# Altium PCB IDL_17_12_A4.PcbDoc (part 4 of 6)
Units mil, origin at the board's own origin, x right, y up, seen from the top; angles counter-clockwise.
Board outline 3172.06 x 10350 mil, 6 copper layers (Top Signal, Mid Signal, 3.3 Volt, GND, 5 Volt, Bot Signal), stack 122.8 mil thick; 332 components, 120 nets, 1937 pads, 197 vias.
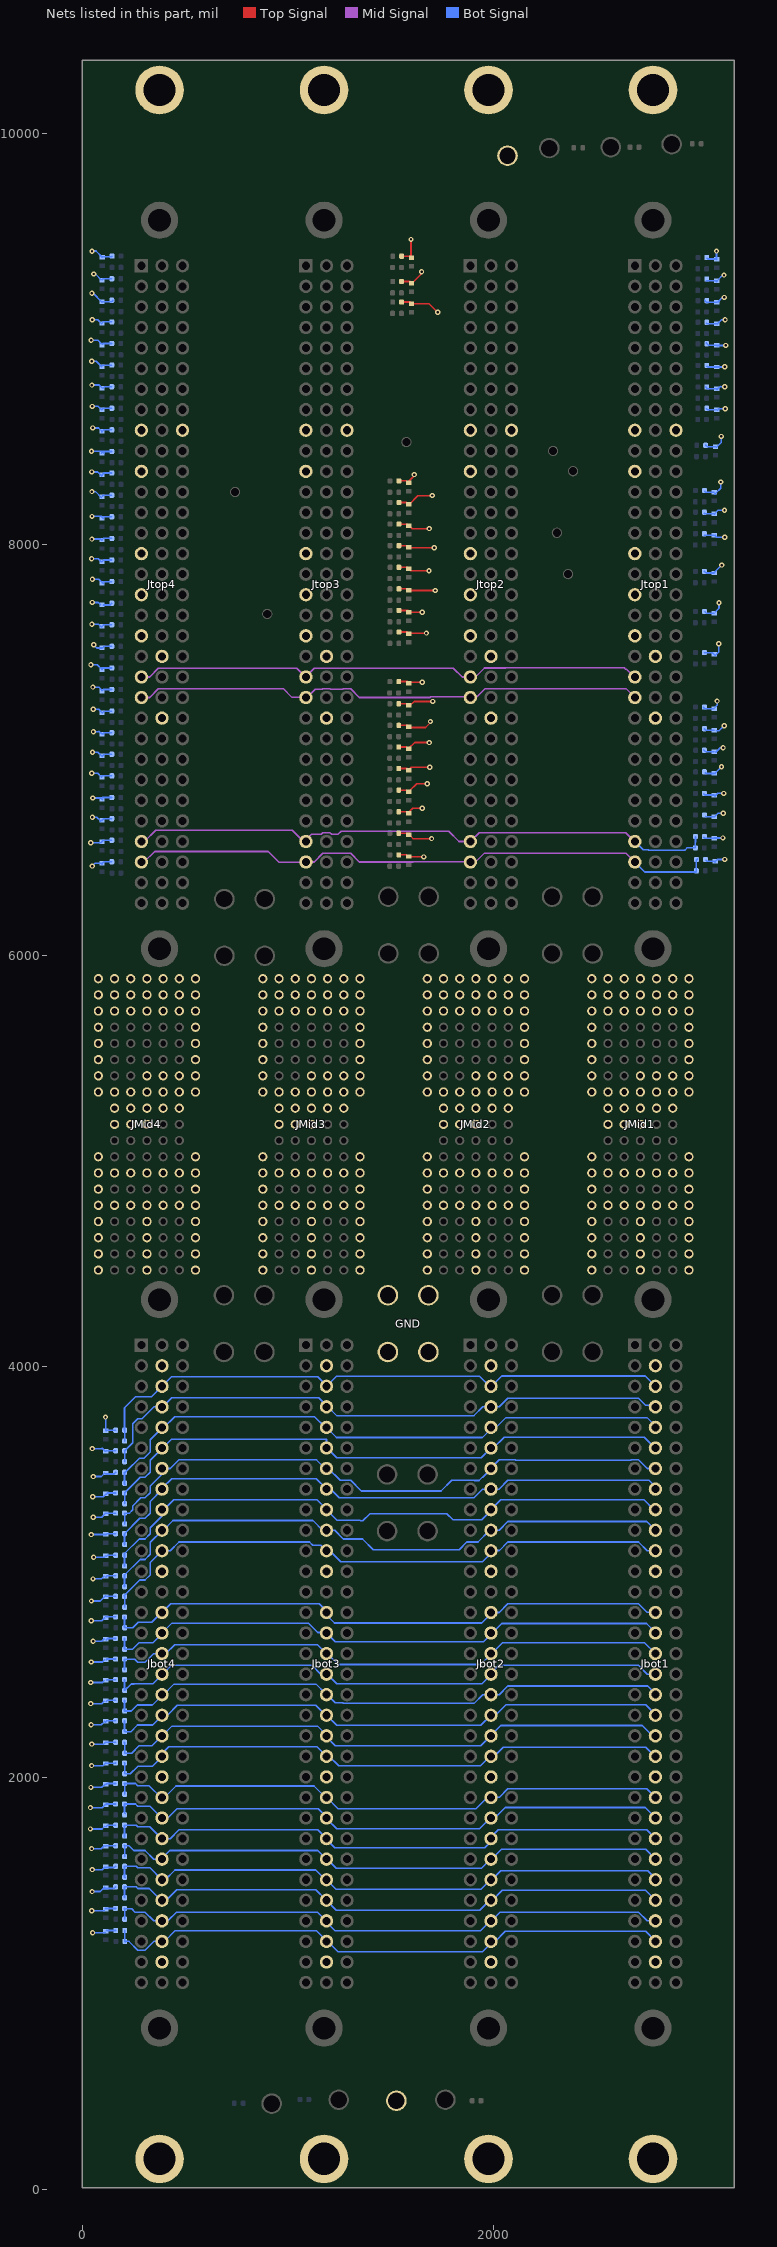
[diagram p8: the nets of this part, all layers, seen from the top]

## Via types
v1: diameter 25.59, hole 12, Top Signal to Bot Signal, 197 vias

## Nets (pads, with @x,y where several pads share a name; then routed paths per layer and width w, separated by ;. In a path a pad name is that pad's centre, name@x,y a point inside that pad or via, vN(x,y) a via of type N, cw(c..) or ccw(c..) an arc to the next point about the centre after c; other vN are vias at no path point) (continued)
GND: CR_IDL_17_12_TerA1.1 CR_IDL_17_12_TerA2.1 CR_IDL_17_12_TerA3.1 CR_IDL_17_12_TerA4.1 CR_IDL_17_12_TerA5.1 CR_IDL_17_12_TerA6.1 CR_IDL_17_12_TerA7.1 CR_IDL_17_12_TerA8.1 CR_IDL_17_12_TerA9.1 CR_IDL_17_12_TerA10.1 CR_IDL_17_12_TerA11.1 CR_IDL_17_12_TerA12.1 CR_IDL_17_12_TerA13.1 CR_IDL_17_12_TerA14.1 CR_IDL_17_12_TerA15.1 CR_IDL_17_12_TerA16.1 CR_IDL_17_12_TerA17.1 CR_IDL_17_12_TerA18.1 CR_IDL_17_12_TerA19.1 CR_IDL_17_12_TerA20.1 CR_IDL_17_12_TerA21.1 CR_IDL_17_12_TerA22.1 CR_IDL_17_12_TerA23.1 CR_IDL_17_12_TerA24.1 CR_IDL_17_12_TerA25.1 CR_IDL_17_12_TerA26.1 CR_IDL_17_12_TerA27.1 CR_IDL_17_12_TerA28.1 CR_IDL_17_12_TerA29.1 CR_IDL_17_12_TerA30.1 CR_IDL_17_12_TerA31.1 CR_IDL_17_12_TerA32.1 CR_IDL_17_12_TerA33.1 CR_IDL_17_12_TerA34.1 CR_IDL_17_12_TerA35.1 CR_IDL_17_12_TerA36.1 CR_IDL_17_12_TerA37.1 CR_IDL_17_12_TerA38.1 CR_IDL_17_12_TerA39.1 CR_IDL_17_12_TerA40.1 CR_IDL_17_12_TerA41.1 CR_IDL_17_12_TerA42.1 CR_IDL_17_12_TerA43.1 CR_IDL_17_12_TerA44.1 CR_IDL_17_12_TerA45.1 CR_IDL_17_12_TerA46.1 CR_IDL_17_12_TerA47.1 CR_IDL_17_12_TerA48.1 CR_IDL_17_12_TerA49.1 CR_IDL_17_12_TerA50.1 CR_IDL_17_12_TerA51.1 CR_IDL_17_12_TerA52.1 CR_IDL_17_12_TerA53.1 CR_IDL_17_12_TerA54.1 CR_IDL_17_12_TerA55.1 CR_IDL_17_12_TerA56.1 CR_IDL_17_12_TerA57.1 CR_IDL_17_12_TerA58.1 CR_IDL_17_12_TerA59.1 CR_IDL_17_12_TerA60.1 CR_IDL_17_12_TerA61.1 CR_IDL_17_12_TerA62.1 CR_IDL_17_12_TerA63.1 CR_IDL_17_12_TerA64.1 CR_IDL_17_12_TerA65.1 CR_IDL_17_12_TerA66.1 CR_IDL_17_12_TerA67.1 CR_IDL_17_12_TerA68.1 CR_IDL_17_12_TerA69.1 CR_IDL_17_12_TerA70.1 CR_IDL_17_12_TerA71.1 CR_IDL_17_12_TerA72.1 CRB_IDL_17_12_TerB1.1 CRB_IDL_17_12_TerB2.1 CRB_IDL_17_12_TerB3.1 CRB_IDL_17_12_TerB4.1 CRB_IDL_17_12_TerB5.1 CRB_IDL_17_12_TerB6.1 CRB_IDL_17_12_TerB7.1 CRB_IDL_17_12_TerB8.1 CRB_IDL_17_12_TerB9.1 CRB_IDL_17_12_TerB10.1 CRB_IDL_17_12_TerB11.1 CRB_IDL_17_12_TerB12.1 CRB_IDL_17_12_TerB13.1 CRB_IDL_17_12_TerB14.1 CRB_IDL_17_12_TerB15.1 CRB_IDL_17_12_TerB16.1 CRB_IDL_17_12_TerB17.1 CRB_IDL_17_12_TerB18.1 CRB_IDL_17_12_TerB19.1 CRB_IDL_17_12_TerB20.1 CRB_IDL_17_12_TerB21.1 CRB_IDL_17_12_TerB22.1 CRB_IDL_17_12_TerB23.1 CRB_IDL_17_12_TerB24.1 CRB_IDL_17_12_TerB25.1 GND.1 GND.2 GND.3 GND.4 Jbot1.B2 Jbot1.B12 Jbot1.B22 Jbot1.B31 Jbot2.B2 Jbot2.B12 Jbot2.B22 Jbot2.B31 Jbot3.B2 Jbot3.B12 Jbot3.B22 Jbot3.B31 Jbot4.B2 Jbot4.B12 Jbot4.B22 Jbot4.B31 JMid1.1 JMid1.2 JMid1.3 JMid1.4 JMid1.5 JMid1.6 JMid1.7 JMid1.8 JMid1.9 JMid1.10 JMid1.11 JMid1.12 JMid1.13 JMid1.14 JMid1.15 JMid1.16 JMid1.17 JMid1.18 JMid1.19 JMid1.24 JMid1.25 JMid1.26 JMid1.29 JMid1.31 JMid1.36 JMid1.37 JMid1.38 JMid1.43 JMid1.44 JMid1.45 JMid1.48 JMid1.50 JMid1.55 JMid1.56 JMid1.57 JMid1.61 JMid1.62 JMid1.63 JMid1.64 JMid1.67 JMid1.69 JMid1.70 JMid1.71 JMid1.72 JMid1.73 JMid1.74 JMid1.75 JMid1.76 JMid1.80 JMid1.81 JMid1.82 JMid1.86 JMid1.88 JMid1.93 JMid1.94 JMid1.95 JMid1.99 JMid1.100 JMid1.101 JMid1.105 JMid1.107 JMid1.112 JMid1.113 JMid1.114 JMid1.115 JMid1.116 JMid1.117 JMid1.118 JMid1.119 JMid1.120 JMid1.121 JMid1.122 JMid1.123 JMid1.124 JMid1.125 JMid1.126 JMid1.127 JMid2.1 JMid2.2 JMid2.3 JMid2.4 JMid2.5 JMid2.6 JMid2.7 JMid2.8 JMid2.9 JMid2.10 JMid2.11 JMid2.12 JMid2.13 JMid2.14 JMid2.15 JMid2.16 JMid2.17 JMid2.18 JMid2.19 JMid2.24 JMid2.25 JMid2.26 JMid2.29 JMid2.31 JMid2.36 JMid2.37 JMid2.38 JMid2.43 JMid2.44 JMid2.45 JMid2.48 JMid2.50 JMid2.55 JMid2.56 JMid2.57 JMid2.61 JMid2.62 JMid2.63 JMid2.64 JMid2.67 JMid2.69 JMid2.70 JMid2.71 JMid2.72 JMid2.73 JMid2.74 JMid2.75 JMid2.76 JMid2.80 JMid2.81 JMid2.82 JMid2.86 JMid2.88 JMid2.93 JMid2.94 JMid2.95 JMid2.99 JMid2.100 JMid2.101 JMid2.105 JMid2.107 JMid2.112 JMid2.113 JMid2.114 JMid2.115 JMid2.116 JMid2.117 JMid2.118 JMid2.119 JMid2.120 JMid2.121 JMid2.122 JMid2.123 JMid2.124 JMid2.125 JMid2.126 JMid2.127 JMid3.1 JMid3.2 JMid3.3 JMid3.4 JMid3.5 JMid3.6 JMid3.7 JMid3.8 JMid3.9 JMid3.10 JMid3.11 JMid3.12 JMid3.13 JMid3.14 JMid3.15 JMid3.16 JMid3.17 JMid3.18 JMid3.19 JMid3.24 JMid3.25 JMid3.26 JMid3.29 JMid3.31 JMid3.36 JMid3.37 JMid3.38 JMid3.43 JMid3.44 JMid3.45 JMid3.48 JMid3.50 JMid3.55 JMid3.56 JMid3.57 JMid3.61 JMid3.62 JMid3.63 JMid3.64 JMid3.67 JMid3.69 JMid3.70 JMid3.71 JMid3.72 JMid3.73 JMid3.74 JMid3.75 JMid3.76 JMid3.80 JMid3.81 JMid3.82 JMid3.86 JMid3.88 JMid3.93 JMid3.94 JMid3.95 JMid3.99 JMid3.100 JMid3.101 JMid3.105 JMid3.107 JMid3.112 JMid3.113 JMid3.114 JMid3.115 JMid3.116 JMid3.117 JMid3.118 JMid3.119 JMid3.120 JMid3.121 JMid3.122 JMid3.123 JMid3.124 JMid3.125 JMid3.126 JMid3.127 JMid4.1 JMid4.2 JMid4.3 JMid4.4 JMid4.5 JMid4.6 JMid4.7 JMid4.8 JMid4.9 JMid4.10 JMid4.11 JMid4.12 JMid4.13 JMid4.14 JMid4.15 JMid4.16 JMid4.17 JMid4.18 JMid4.19 JMid4.24 JMid4.25 JMid4.26 JMid4.29 JMid4.31 JMid4.36 JMid4.37 JMid4.38 JMid4.43 JMid4.44 JMid4.45 JMid4.48 JMid4.50 JMid4.55 JMid4.56 JMid4.57 JMid4.61 JMid4.62 JMid4.63 JMid4.64 JMid4.67 JMid4.69 JMid4.70 JMid4.71 JMid4.72 JMid4.73 JMid4.74 JMid4.75 JMid4.76 JMid4.80 JMid4.81 JMid4.82 JMid4.86 JMid4.88 JMid4.93 JMid4.94 JMid4.95 JMid4.99 JMid4.100 JMid4.101 JMid4.105 JMid4.107 JMid4.112 JMid4.113 JMid4.114 JMid4.115 JMid4.116 JMid4.117 JMid4.118 JMid4.119 JMid4.120 JMid4.121 JMid4.122 JMid4.123 JMid4.124 JMid4.125 JMid4.126 JMid4.127 Jtop1.A9 Jtop1.A11 Jtop1.A15 Jtop1.A17 Jtop1.A19 Jtop1.B20 Jtop1.B23 Jtop1.C9 Jtop2.A9 Jtop2.A11 Jtop2.A15 Jtop2.A17 Jtop2.A19 Jtop2.B20 Jtop2.B23 Jtop2.C9 Jtop3.A9 Jtop3.A11 Jtop3.A15 Jtop3.A17 Jtop3.A19 Jtop3.B20 Jtop3.B23 Jtop3.C9 Jtop4.A9 Jtop4.A11 Jtop4.A15 Jtop4.A17 Jtop4.A19 Jtop4.B20 Jtop4.B23 Jtop4.C9 pad.M3 R2R_IDL_17_12_TerA1.1 R2R_IDL_17_12_TerA2.1 R2R_IDL_17_12_TerA3.1 R2R_IDL_17_12_TerA4.1 R2R_IDL_17_12_TerA5.1 R2R_IDL_17_12_TerA6.1 R2R_IDL_17_12_TerA7.1 R2R_IDL_17_12_TerA8.1 R2R_IDL_17_12_TerA9.1 R2R_IDL_17_12_TerA10.1 R2R_IDL_17_12_TerA11.1 R2R_IDL_17_12_TerA12.1 R2R_IDL_17_12_TerA13.1 R2R_IDL_17_12_TerA14.1 R2R_IDL_17_12_TerA15.1 R2R_IDL_17_12_TerA16.1 R2R_IDL_17_12_TerA17.1 R2R_IDL_17_12_TerA18.1 R2R_IDL_17_12_TerA19.1 R2R_IDL_17_12_TerA20.1 R2R_IDL_17_12_TerA21.1 R2R_IDL_17_12_TerA22.1 R2R_IDL_17_12_TerA23.1 R2R_IDL_17_12_TerA24.1 R2R_IDL_17_12_TerA25.1 R2R_IDL_17_12_TerA26.1 R2R_IDL_17_12_TerA27.1 R2R_IDL_17_12_TerA28.1 R2R_IDL_17_12_TerA29.1 R2R_IDL_17_12_TerA30.1 R2R_IDL_17_12_TerA31.1 R2R_IDL_17_12_TerA32.1 R2R_IDL_17_12_TerA33.1 R2R_IDL_17_12_TerA34.1 R2R_IDL_17_12_TerA35.1 R2R_IDL_17_12_TerA36.1 R2R_IDL_17_12_TerA37.1 R2R_IDL_17_12_TerA38.1 R2R_IDL_17_12_TerA39.1 R2R_IDL_17_12_TerA40.1 R2R_IDL_17_12_TerA41.1 R2R_IDL_17_12_TerA42.1 R2R_IDL_17_12_TerA43.1 R2R_IDL_17_12_TerA44.1 R2R_IDL_17_12_TerA45.1 R2R_IDL_17_12_TerA46.1 R2R_IDL_17_12_TerA47.1 R2R_IDL_17_12_TerA48.1 R2R_IDL_17_12_TerA49.1 R2R_IDL_17_12_TerA50.1 R2R_IDL_17_12_TerA51.1 R2R_IDL_17_12_TerA52.1 R2R_IDL_17_12_TerA53.1 R2R_IDL_17_12_TerA54.1 R2R_IDL_17_12_TerA55.1 R2R_IDL_17_12_TerA56.1 R2R_IDL_17_12_TerA57.1 R2R_IDL_17_12_TerA58.1 R2R_IDL_17_12_TerA59.1 R2R_IDL_17_12_TerA60.1 R2R_IDL_17_12_TerA61.1 R2R_IDL_17_12_TerA62.1 R2R_IDL_17_12_TerA63.1 R2R_IDL_17_12_TerA64.1 R2R_IDL_17_12_TerA65.1 R2R_IDL_17_12_TerA66.1 R2R_IDL_17_12_TerA67.1 R2R_IDL_17_12_TerA68.1 R2R_IDL_17_12_TerA69.1 R2R_IDL_17_12_TerA70.1 R2R_IDL_17_12_TerA71.1 R2R_IDL_17_12_TerA72.1 R2RB_IDL_17_12_TerB1.1 R2RB_IDL_17_12_TerB2.1 R2RB_IDL_17_12_TerB3.1 R2RB_IDL_17_12_TerB4.1 R2RB_IDL_17_12_TerB5.1 R2RB_IDL_17_12_TerB6.1 R2RB_IDL_17_12_TerB7.1 R2RB_IDL_17_12_TerB8.1 R2RB_IDL_17_12_TerB9.1 R2RB_IDL_17_12_TerB10.1 R2RB_IDL_17_12_TerB11.1 R2RB_IDL_17_12_TerB12.1 R2RB_IDL_17_12_TerB13.1 R2RB_IDL_17_12_TerB14.1 R2RB_IDL_17_12_TerB15.1 R2RB_IDL_17_12_TerB16.1 R2RB_IDL_17_12_TerB17.1 R2RB_IDL_17_12_TerB18.1 R2RB_IDL_17_12_TerB19.1 R2RB_IDL_17_12_TerB20.1 R2RB_IDL_17_12_TerB21.1 R2RB_IDL_17_12_TerB22.1 R2RB_IDL_17_12_TerB23.1 R2RB_IDL_17_12_TerB24.1 R2RB_IDL_17_12_TerB25.1 | length 11341.6
  Top Signal w8: R2R_IDL_17_12_TerA24.1@1539.78,6489.66 1577.33,6489.66 CR_IDL_17_12_TerA24.1@1586.48,6480.51 ; R2R_IDL_17_12_TerA25.1@1539.78,6594.66 1587.86,6594.66 CR_IDL_17_12_TerA25.1@1593.87,6594.66 ; R2R_IDL_17_12_TerA26.1@1539.78,6699.66 1581.86,6699.66 1588.74,6692.77 CR_IDL_17_12_TerA26.1@1589.45,6692.07 ; R2R_IDL_17_12_TerA27.1@1539.78,6804.66 1577.23,6804.66 1586.43,6795.46 CR_IDL_17_12_TerA27.1@1586.49,6795.4 ; R2R_IDL_17_12_TerA28.1@1539.78,6909.66 1579.99,6909.66 CR_IDL_17_12_TerA28.1@1584.99,6904.66 ; R2R_IDL_17_12_TerA29.1@1539.78,7014.66 1576.84,7014.66 CR_IDL_17_12_TerA29.1@1586,7005.49 ; R2R_IDL_17_12_TerA30.1@1539.78,7119.66 1584.02,7119.66 1589.83,7113.85 CR_IDL_17_12_TerA30.1@1591.41,7112.27 ; R2R_IDL_17_12_TerA31.1@1539.78,7224.66 1582.35,7224.66 CR_IDL_17_12_TerA31.1@1587.97,7219.04 ; R2R_IDL_17_12_TerA32.1@1539.78,7332.66 1582.31,7332.66 CR_IDL_17_12_TerA32.1@1588.43,7326.54 ; R2R_IDL_17_12_TerA33.1@1540.73,7573.55 1581.12,7573.55 CR_IDL_17_12_TerA33.1@1586.05,7568.62 ; R2R_IDL_17_12_TerA34.1@1540.73,7678.55 1585.01,7678.55 1590.8,7672.76 CR_IDL_17_12_TerA34.1@1592.32,7671.25 ; R2R_IDL_17_12_TerA35.1@1540.73,7783.55 1584.44,7783.55 CR_IDL_17_12_TerA35.1@1590.51,7777.48 ; R2R_IDL_17_12_TerA36.1@1540.73,7888.55 1581.19,7888.55 1586.4,7883.34 CR_IDL_17_12_TerA36.1@1588.75,7881 ; R2R_IDL_17_12_TerA37.1@1540.73,7993.55 CR_IDL_17_12_TerA37.1@1584.89,7993.55 ; R2R_IDL_17_12_TerA38.1@1540.73,8098.55 1580.95,8098.55 CR_IDL_17_12_TerA38.1@1583.39,8096.11 ; R2R_IDL_17_12_TerA39.1@1540.73,8203.55 1579.48,8203.55 CR_IDL_17_12_TerA39.1@1587.85,8195.18 ; R2R_IDL_17_12_TerA40.1@1540.73,8308.55 1576.23,8308.55 CR_IDL_17_12_TerA40.1@1585.25,8299.53 ; R2R_IDL_17_12_TerA43.1@1553.71,9401.49 1593.03,9401.49 CR_IDL_17_12_TerA43.1@1599.28,9395.24 ; R2R_IDL_17_12_TerA41.1@1553.78,9178.52 1594.96,9178.52 CR_IDL_17_12_TerA41.1@1601.85,9171.63 ; R2R_IDL_17_12_TerA42.1@1553.78,9278.52 1595.14,9278.52 1602.38,9271.27 CR_IDL_17_12_TerA42.1@1603.9,9269.75 ; CR_IDL_17_12_TerA36.1@1584.63,7881.57 1587.12,7879.09 1592.23,7873.98 CR_IDL_17_12_TerA36.1@1594.79,7873.98 ; CR_IDL_17_12_TerA28.1@1584.83,6904.66 CR_IDL_17_12_TerA28.1@1584.99,6904.66 ; CR_IDL_17_12_TerA37.1@1584.89,7988.75 1588.34,7985.3 1590.11,7983.53 CR_IDL_17_12_TerA37.1@1590.16,7983.53 ; CR_IDL_17_12_TerA32.1@1585.89,7324 1587.31,7325.43 CR_IDL_17_12_TerA32.1@1588.43,7326.54 ; CR_IDL_17_12_TerA40.1@1588.33,8302.61 1586.66,8304.28 1615.53,8333.15 v1(1615.53,8339.65) ; CR_IDL_17_12_TerA33.1@1589.08,7571.65 1591.88,7568.85 1592.24,7568.49 v1(1674.15,7568.49) ; CR_IDL_17_12_TerA26.1@1589.14,6698 1607.78,6716.64 v1(1654.36,6716.64) ; CR_IDL_17_12_TerA29.1@1589.14,7007.59 1617.63,7036.09 v1(1688.09,7036.09) ; CR_IDL_17_12_TerA35.1@1589.67,7779.23 1590.97,7777.93 1593.31,7775.59 v1(1716.98,7775.59) ; CR_IDL_17_12_TerA37.1@1589.96,7983.33 CR_IDL_17_12_TerA37.1@1590.16,7983.53 ; CR_IDL_17_12_TerA30.1@1591.1,7108.97 1669.54,7108.97 1694.04,7133.47 v1(1694.04,7138.4) ; CR_IDL_17_12_TerA39.1@1591.21,8194.23 1632.91,8235.94 1700.37,8235.94 v1(1702.16,8237.73) ; CR_IDL_17_12_TerA38.1@1591.44,8088.97 1604.71,8075.71 1605.76,8076.77 v1(1688.34,8076.77) ; CR_IDL_17_12_TerA24.1@1591.68,6482.44 1594.38,6479.74 v1(1661.47,6479.74) ; CR_IDL_17_12_TerA31.1@1592.27,7213.47 1614.66,7235.86 v1(1704.54,7235.86) ; CR_IDL_17_12_TerA34.1@1592.86,7669.2 1592.99,7669.33 v1(1653.61,7669.33) ; CR_IDL_17_12_TerA36.1@1592.86,7875.91 CR_IDL_17_12_TerA36.1@1594.79,7873.98 ; CR_IDL_17_12_TerA25.1@1593.53,6584.82 1609.38,6568.97 v1(1699.33,6568.97) ; CR_IDL_17_12_TerA27.1@1593.84,6803.28 1626.69,6836.14 1627.56,6835.27 v1(1678.84,6835.27) ; CR_IDL_17_12_TerA43.1@1598.62,9394.55 CR_IDL_17_12_TerA43.1@1599.28,9395.21 ; v1(1599.28,9482.96) CR_IDL_17_12_TerA43.1@1599.28,9395.24 ; CR_IDL_17_12_TerA41.1@1601.86,9170.75 1687.03,9170.75 v1@1727.55,9130.23 ; CR_IDL_17_12_TerA42.1@1604.46,9269.59 1650.65,9315.78 v1(1650.65,9326.13) ; CR_IDL_17_12_TerA43.1@1606.42,9388.1 1601.3,9393.22 CR_IDL_17_12_TerA43.1@1599.28,9395.24 ; v1(1654.12,7329.81) 1591.7,7329.81 CR_IDL_17_12_TerA32.1@1588.43,7326.54 ; v1(1686.92,7871.49) 1597.28,7871.49 CR_IDL_17_12_TerA36.1@1594.79,7873.98 ; v1(1690.96,6916.44) 1598.96,6916.44 1587.18,6904.66 CR_IDL_17_12_TerA28.1@1584.99,6904.66 ; v1@1706.34,7989.65 v1(1712.46,7983.53) CR_IDL_17_12_TerA37.1@1590.16,7983.53
  Bot Signal w8: v1(40.29,1751.86) 96.56,1751.86 CRB_IDL_17_12_TerB6.1@110.55,1765.85 ; v1(40.29,1855.71) 97.4,1855.71 113.21,1871.52 CRB_IDL_17_12_TerB7.1@114.22,1872.53 ; v1(41.59,2464.32) 96.83,2464.32 97.41,2463.74 CRB_IDL_17_12_TerB13.1@106.43,2472.77 ; v1(41.66,2361.56) 94.81,2361.56 CRB_IDL_17_12_TerB12.1@105.98,2372.73 ; v1(41.74,6549.1) 91.84,6549.1 CR_IDL_17_12_TerA45.1@95.17,6552.44 ; v1(42.34,1954.03) 95.91,1954.03 CRB_IDL_17_12_TerB8.1@111.7,1969.82 ; v1(42.68,7414.54) 72.97,7414.54 96.2,7391.31 CR_IDL_17_12_TerA53.1@96.35,7391.16 ; v1(43.17,8992.38) 76.64,8992.38 CR_IDL_17_12_TerA68.1@93.35,8975.67 ; v1(43.3,2258.66) 92.4,2258.66 CRB_IDL_17_12_TerB11.1@108.26,2274.52 ; v1(43.79,2764.04) 95.06,2764.04 CRB_IDL_17_12_TerB16.1@109.87,2778.84 ; v1(44.08,2563.93) 96.35,2563.93 97.41,2562.87 CRB_IDL_17_12_TerB14.1@108.95,2574.41 ; v1(44.12,3184.02) 114.44,3184.02 115.33,3184.02 115.52,3184.2 CRB_IDL_17_12_TerB20.1@117.19,3185.88 ; v1(44.78,2860.62) 88.17,2860.62 111.14,2883.59 CRB_IDL_17_12_TerB17.1@113.99,2886.44 ; v1(45.27,8452.66) 96.11,8452.66 97.02,8452.66 CR_IDL_17_12_TerA63.1@100.01,8449.67 ; v1(45.49,2060.2) 102.73,2060.2 113.62,2071.1 CRB_IDL_17_12_TerB9.1@115.13,2072.61 ; v1(45.64,1656.31) 93.27,1656.31 CRB_IDL_17_12_TerB5.1@106.66,1669.7 ; v1(45.91,7930.12) 77.61,7930.12 CR_IDL_17_12_TerA58.1@92.27,7915.45 ; v1(45.96,8890.57) 68.27,8890.57 CR_IDL_17_12_TerA67.1@94.49,8864.35 ; v1(46.34,6886.77) 75.6,6886.77 CR_IDL_17_12_TerA48.1@93.68,6868.69 ; v1(46.56,2164.73) 104.7,2164.73 CRB_IDL_17_12_TerB10.1@110.55,2170.59 ; v1(46.66,8352.25) 75.18,8352.25 92.16,8335.27 CR_IDL_17_12_TerA62.1@95.67,8331.76 ; v1(46.82,1354.24) 106.66,1354.24 CRB_IDL_17_12_TerB2.1@107.58,1355.15 ; v1(47.35,8025.95) 90.1,8025.95 CR_IDL_17_12_TerA59.1@95.46,8020.59 ; v1(47.36,8256.72) 64.77,8256.72 93.19,8228.3 CR_IDL_17_12_TerA61.1@93.29,8228.2 ; v1(47.36,8774.82) 82.51,8774.82 CR_IDL_17_12_TerA66.1@96.01,8761.32 ; v1(47.36,9221.79) 53.18,9221.79 95.93,9179.04 CR_IDL_17_12_TerA70.1@97.69,9177.28 ; v1(47.53,7611.43) 78.33,7611.43 79.07,7612.18 93.07,7598.18 CR_IDL_17_12_TerA55.1@93.29,7597.96 ; v1(47.84,8136.08) 93.04,8136.08 CR_IDL_17_12_TerA60.1@99.44,8129.69 ; v1(48.01,1447.41) 87.43,1447.41 CRB_IDL_17_12_TerB3.1@109.18,1469.16 ; v1@48.34,6435.27 48.82,6435.76 61.28,6448.21 CR_IDL_17_12_TerA44.1@96.11,6448.21 ; v1(48.6,1554.23) 96.93,1554.23 97.41,1553.76 CRB_IDL_17_12_TerB4.1@109.18,1565.54 ; v1(49.09,7717.48) 78.02,7717.48 CR_IDL_17_12_TerA56.1@89.22,7706.28 ; v1(49.36,3602.05) 96.38,3602.05 97.41,3603.08 CRB_IDL_17_12_TerB24.1@111.7,3588.79 ; v1(49.45,8670.92) 78.43,8670.92 CR_IDL_17_12_TerA65.1@93.29,8656.05 ; v1(49.45,9092.09) 76.13,9092.09 CR_IDL_17_12_TerA69.1@93.81,9074.42 ; v1@49.47,9426.75 67.34,9426.75 CR_IDL_17_12_TerA72.1@95.56,9398.53 ; v1(49.7,7829.95) 81.34,7829.95 CR_IDL_17_12_TerA57.1@97.2,7814.09 ; v1(49.8,6672.75) 70.5,6672.75 89.13,6654.12 CR_IDL_17_12_TerA46.1@92.92,6657.91 ; v1(50.13,6989.51) 76.25,6989.51 95.33,6970.43 CR_IDL_17_12_TerA49.1@97.37,6968.39 ; v1(50.57,1247.5) 109.13,1247.5 CRB_IDL_17_12_TerB1.1@111.7,1250.08 ; v1(50.84,8566.32) 79.79,8566.32 96.5,8549.61 CR_IDL_17_12_TerA64.1@97.34,8548.77 ; v1(51.04,6766.37) 90.6,6766.37 95.94,6761.04 CR_IDL_17_12_TerA47.1@98.61,6758.37 ; v1(51.32,3367.19) 101.86,3367.19 CRB_IDL_17_12_TerB22.1@113.3,3378.63 ; v1@52.09,7301.01 v1(52.09,7305.87) 80.44,7305.87 90.13,7296.19 CR_IDL_17_12_TerA52.1@97.2,7289.12 ; v1(52.63,2968.13) 93.35,2968.13 CRB_IDL_17_12_TerB18.1@107.12,2981.9 ; v1(52.8,2664.78) 94.93,2664.78 CRB_IDL_17_12_TerB15.1@106.66,2676.51 ; v1(53.28,3268.41) 94.65,3268.41 CRB_IDL_17_12_TerB21.1@111.24,3285 ; v1(53.26,7198.1) 79.89,7198.1 CR_IDL_17_12_TerA51.1@95.33,7182.66 ; v1(53.94,3465.98) 93.51,3465.98 CRB_IDL_17_12_TerB23.1@110.33,3482.79 ; v1(54.55,7088.89) 79.26,7088.89 81.66,7091.28 CR_IDL_17_12_TerA50.1@94.57,7078.37 ; v1(55.25,3073.46) 107.1,3073.46 CRB_IDL_17_12_TerB19.1@113.07,3079.42 ; v1(55.73,7511.15) v1@56.23,7511.15 ; v1@56.23,7510.81 70.83,7496.21 CR_IDL_17_12_TerA54.1@96.11,7496.21 ; v1(56.65,9315.03) 64.4,9315.03 CR_IDL_17_12_TerA71.1@91.75,9287.68 ; CR_IDL_17_12_TerA63.1@92.7,8442.35 95.34,8444.99 CR_IDL_17_12_TerA63.1@100.01,8449.67 ; CR_IDL_17_12_TerA69.1@93.37,9073.78 94.96,9075.36 101.58,9081.99 R2R_IDL_17_12_TerA69.1@144.19,9081.99 ; CR_IDL_17_12_TerA72.1@93.37,9398.53 CR_IDL_17_12_TerA72.1@95.56,9398.53 ; CR_IDL_17_12_TerA46.1@93.68,6658.66 95.12,6657.23 CR_IDL_17_12_TerA46.1@97.09,6655.25 ; CR_IDL_17_12_TerA62.1@94.54,8337.65 CR_IDL_17_12_TerA62.1@97.03,8335.16 ; CR_IDL_17_12_TerA53.1@94.71,7397.78 95.91,7398.99 96.11,7398.99 R2R_IDL_17_12_TerA53.1@144.19,7398.99 ; CR_IDL_17_12_TerA64.1@94.71,8546.14 96.95,8548.38 CR_IDL_17_12_TerA64.1@97.34,8548.77 ; CR_IDL_17_12_TerA44.1@95.18,6445.61 CR_IDL_17_12_TerA44.1@96.1,6444.69 ; CR_IDL_17_12_TerA45.1@95.38,6553.43 95.64,6553.69 102.94,6560.99 R2R_IDL_17_12_TerA45.1@144.19,6560.99 ; CR_IDL_17_12_TerA65.1@95.38,8654.61 95.54,8654.78 102.75,8661.99 R2R_IDL_17_12_TerA65.1@144.19,8661.99 ; CR_IDL_17_12_TerA59.1@95.67,8020.38 CR_IDL_17_12_TerA59.1@95.47,8020.58 ; CR_IDL_17_12_TerA47.1@96.05,6766.36 98.68,6768.99 R2R_IDL_17_12_TerA47.1@144.19,6768.99 ; CR_IDL_17_12_TerA52.1@96.05,7287.97 CR_IDL_17_12_TerA52.1@97.2,7289.12 ; CR_IDL_17_12_TerA55.1@96.05,7600 96.68,7600.64 105.03,7608.99 R2R_IDL_17_12_TerA55.1@144.19,7608.99 ; CR_IDL_17_12_TerA58.1@96.05,7914.71 96.83,7915.49 105.32,7923.99 R2R_IDL_17_12_TerA58.1@144.19,7923.99 ; CR_IDL_17_12_TerA70.1@96.11,9179.21 142.56,9179.21 147.26,9183.92 R2R_IDL_17_12_TerA70.1@150.28,9186.94 ; CR_IDL_17_12_TerA48.1@96.22,6873.99 R2R_IDL_17_12_TerA48.1@144.19,6873.99 ; CR_IDL_17_12_TerA62.1@97.26,8340.36 CR_IDL_17_12_TerA62.1@98.73,8338.9 ; CR_IDL_17_12_TerA61.1@97.39,8233.44 102.94,8238.99 R2R_IDL_17_12_TerA61.1@144.19,8238.99 ; CR_IDL_17_12_TerA72.1@97.42,9396.67 CR_IDL_17_12_TerA72.1@95.56,9398.53 ; CR_IDL_17_12_TerA44.1@98.06,6448.3 105.74,6455.99 R2R_IDL_17_12_TerA44.1@144.19,6455.99 ; CR_IDL_17_12_TerA46.1@98.06,6658.55 105.49,6665.99 R2R_IDL_17_12_TerA46.1@144.19,6665.99 ; CR_IDL_17_12_TerA49.1@98.07,6969.25 107.8,6978.99 R2R_IDL_17_12_TerA49.1@144.19,6978.99 ; CR_IDL_17_12_TerA68.1@98.06,8974.01 101.04,8976.99 R2R_IDL_17_12_TerA68.1@144.19,8976.99 ; CR_IDL_17_12_TerA71.1@98.06,9287.38 102.67,9291.99 R2R_IDL_17_12_TerA71.1@144.19,9291.99 ; CR_IDL_17_12_TerA51.1@98.28,7179.72 107.55,7188.99 R2R_IDL_17_12_TerA51.1@144.19,7188.99 ; CR_IDL_17_12_TerA67.1@99.15,8871.99 R2R_IDL_17_12_TerA67.1@144.19,8871.99 ; CR_IDL_17_12_TerA50.1@99.4,7077.05 106.33,7083.99 R2R_IDL_17_12_TerA50.1@144.19,7083.99 ; CR_IDL_17_12_TerA54.1@101.4,7497.55 107.84,7503.99 R2R_IDL_17_12_TerA54.1@144.19,7503.99 ; CR_IDL_17_12_TerA66.1@101.4,8759.74 108.65,8766.99 R2R_IDL_17_12_TerA66.1@144.19,8766.99 ; CR_IDL_17_12_TerA57.1@101.78,7809.51 98.09,7813.2 CR_IDL_17_12_TerA57.1@97.2,7814.09 ; CR_IDL_17_12_TerA56.1@102.07,7705.13 135.33,7705.13 R2R_IDL_17_12_TerA56.1@144.19,7713.99 ; CR_IDL_17_12_TerA62.1@102.07,8343.25 105.81,8346.99 R2R_IDL_17_12_TerA62.1@144.19,8346.99 ; CR_IDL_17_12_TerA60.1@103.14,8125.99 99.51,8129.62 CR_IDL_17_12_TerA60.1@99.44,8129.69 ; CRB_IDL_17_12_TerB3.1@104.1,1462.4 114.44,1462.4 154.85,1462.4 R2RB_IDL_17_12_TerB3.1@162.75,1470.3 ; CR_IDL_17_12_TerA63.1@105.86,8443.82 100.79,8448.89 CR_IDL_17_12_TerA63.1@100.01,8449.67 ; CRB_IDL_17_12_TerB21.1@107.67,3282.73 110.59,3285.65 112.33,3287.39 113.24,3288.3 114.44,3288.3 R2RB_IDL_17_12_TerB21.1@162.75,3288.3 ; CRB_IDL_17_12_TerB4.1@110.88,1564.1 114.44,1564.1 156.56,1564.1 R2RB_IDL_17_12_TerB4.1@162.75,1570.3 ; CRB_IDL_17_12_TerB2.1@111.95,1364.26 CRB_IDL_17_12_TerB2.1@112.2,1364.51 ; CRB_IDL_17_12_TerB2.1@112.21,1364.52 112.98,1365.3 114.44,1365.3 R2RB_IDL_17_12_TerB2.1@162.75,1365.3 ; CRB_IDL_17_12_TerB11.1@112.67,2271.04 115.68,2274.05 119.92,2278.3 R2RB_IDL_17_12_TerB11.1@162.75,2278.3 ; CRB_IDL_17_12_TerB7.1@113.02,1868.86 CRB_IDL_17_12_TerB7.1@114.44,1870.28 117.46,1873.3 R2RB_IDL_17_12_TerB7.1@162.75,1873.3 ; CRB_IDL_17_12_TerB5.1@113.38,1667.95 113.58,1668.15 115.73,1670.3 R2RB_IDL_17_12_TerB5.1@162.75,1670.3 ; CRB_IDL_17_12_TerB10.1@113.38,2171.83 114.84,2173.3 R2RB_IDL_17_12_TerB10.1@162.75,2173.3 ; CRB_IDL_17_12_TerB18.1@114.45,2976.19 116.49,2978.23 121.56,2983.3 R2RB_IDL_17_12_TerB18.1@162.75,2983.3 ; CRB_IDL_17_12_TerB25.1@114.44,3688.28 114.44,3752.47 115.42,3753.44 v1@116.28,3754.3 ; CRB_IDL_17_12_TerB20.1@114.81,3182.81 115.86,3183.86 117.53,3185.54 120.29,3188.3 R2RB_IDL_17_12_TerB20.1@162.75,3188.3 ; CRB_IDL_17_12_TerB6.1@115.16,1761.8 117.54,1764.18 123.66,1770.3 R2RB_IDL_17_12_TerB6.1@162.75,1770.3 ; CRB_IDL_17_12_TerB16.1@115.16,2787.05 118.19,2784.03 118.92,2783.3 R2RB_IDL_17_12_TerB16.1@162.75,2783.3 ; CRB_IDL_17_12_TerB23.1@115.16,3478.29 154.74,3478.29 R2RB_IDL_17_12_TerB23.1@162.75,3486.3 ; CRB_IDL_17_12_TerB17.1@115.52,2883.4 115.63,2883.3 R2RB_IDL_17_12_TerB17.1@162.75,2883.3 ; CRB_IDL_17_12_TerB24.1@115.52,3588.2 118.62,3591.3 R2RB_IDL_17_12_TerB24.1@162.75,3591.3 ; CRB_IDL_17_12_TerB9.1@115.88,2071.91 161.36,2071.91 R2RB_IDL_17_12_TerB9.1@162.75,2073.3 ; CRB_IDL_17_12_TerB15.1@116.23,2671.07 117.44,2672.28 123.45,2678.3 R2RB_IDL_17_12_TerB15.1@162.75,2678.3 ; CRB_IDL_17_12_TerB8.1@116.59,1969.14 120.75,1973.3 R2RB_IDL_17_12_TerB8.1@162.75,1973.3 ; CRB_IDL_17_12_TerB14.1@116.59,2574.01 120.88,2578.3 R2RB_IDL_17_12_TerB14.1@162.75,2578.3 ; CRB_IDL_17_12_TerB12.1@116.95,2371.67 117.5,2372.22 123.57,2378.3 R2RB_IDL_17_12_TerB12.1@162.75,2378.3 ; CRB_IDL_17_12_TerB22.1@117.26,3380.46 123.09,3386.3 R2RB_IDL_17_12_TerB22.1@162.75,3386.3 ; CRB_IDL_17_12_TerB25.1@117.66,3688.12 120.84,3691.3 R2RB_IDL_17_12_TerB25.1@162.75,3691.3 ; CRB_IDL_17_12_TerB1.1@118.02,1258.99 118.67,1258.34 119.19,1257.82 R2RB_IDL_17_12_TerB1.1@163.44,1257.82 ; CRB_IDL_17_12_TerB19.1@118.38,3077.89 123.78,3083.3 R2RB_IDL_17_12_TerB19.1@162.75,3083.3 ; CRB_IDL_17_12_TerB13.1@120.87,2476.59 122.58,2478.3 R2RB_IDL_17_12_TerB13.1@162.75,2478.3 ; R2R_IDL_17_12_TerA52.1@144.19,7293.99 102.06,7293.99 CR_IDL_17_12_TerA52.1@97.2,7289.12 ; R2R_IDL_17_12_TerA57.1@144.19,7818.99 102.1,7818.99 CR_IDL_17_12_TerA57.1@97.2,7814.09 ; R2R_IDL_17_12_TerA59.1@144.19,8028.99 103.86,8028.99 CR_IDL_17_12_TerA59.1@96.11,8021.21 CR_IDL_17_12_TerA59.1@95.46,8020.59 ; R2R_IDL_17_12_TerA60.1@144.19,8133.99 103.73,8133.99 CR_IDL_17_12_TerA60.1@99.44,8129.69 ; R2R_IDL_17_12_TerA63.1@144.19,8451.99 102.34,8451.99 CR_IDL_17_12_TerA63.1@100.01,8449.67 ; R2R_IDL_17_12_TerA64.1@144.19,8556.99 105.56,8556.99 CR_IDL_17_12_TerA64.1@97.34,8548.77 ; R2R_IDL_17_12_TerA72.1@145.32,9402.03 141.82,9398.53 97.42,9398.53 CR_IDL_17_12_TerA72.1@95.56,9398.53 ; R2R_IDL_17_12_TerA8.1@3021.77,7207.64 3023.74,7205.66 3028.62,7200.78 CR_IDL_17_12_TerA8.1@3074.72,7200.78 ; R2R_IDL_17_12_TerA4.1@3022.49,6786.7 3023.64,6785.56 3028.41,6780.78 CR_IDL_17_12_TerA4.1@3074.72,6780.78 ; R2R_IDL_17_12_TerA6.1@3022.85,6999.71 3025.32,6997.24 3031.78,6990.78 CR_IDL_17_12_TerA6.1@3074.72,6990.78 ; R2R_IDL_17_12_TerA2.1@3023.36,6575.51 3023.47,6575.39 3028.08,6570.78 CR_IDL_17_12_TerA2.1@3074.72,6570.78 ; R2R_IDL_17_12_TerA7.1@3025.39,7103.49 3025.98,7102.9 3033.1,7095.78 CR_IDL_17_12_TerA7.1@3074.72,7095.78 ; R2R_IDL_17_12_TerA9.1@3026.64,7473.56 3064.81,7473.56 3073.65,7464.72 CR_IDL_17_12_TerA9.1@3079.1,7459.27 ; R2R_IDL_17_12_TerA11.1@3027.08,7868.3 3034.6,7860.78 CR_IDL_17_12_TerA11.1@3074.72,7860.78 ; R2R_IDL_17_12_TerA12.1@3027.08,8044.81 3027.9,8044 CR_IDL_17_12_TerA12.1@3074.35,8044 ; R2R_IDL_17_12_TerA13.1@3027.08,8149.9 3027.99,8149 CR_IDL_17_12_TerA13.1@3074.35,8149 ; R2R_IDL_17_12_TerA14.1@3028.25,8257.9 3032.15,8254 CR_IDL_17_12_TerA14.1@3074.35,8254 ; R2R_IDL_17_12_TerA21.1@3028.25,9186.34 3033.57,9181.01 3036.94,9177.64 3037.98,9177.64 CR_IDL_17_12_TerA21.1@3086.06,9177.64 ; R2R_IDL_17_12_TerA10.1@3029.41,7671.46 3035.08,7665.78 CR_IDL_17_12_TerA10.1@3074.72,7665.78 ; R2R_IDL_17_12_TerA5.1@3030.84,6889.4 3034.45,6885.78 CR_IDL_17_12_TerA5.1@3074.72,6885.78 ; R2R_IDL_17_12_TerA3.1@3032.35,6676.2 3032.77,6675.78 CR_IDL_17_12_TerA3.1@3074.72,6675.78 ; R2R_IDL_17_12_TerA17.1@3032.31,8765.96 3035.42,8762.85 3040.63,8757.64 CR_IDL_17_12_TerA17.1@3086.06,8757.64 ; R2R_IDL_17_12_TerA15.1@3032.89,8483.19 3033.32,8482.76 3042.14,8473.94 CR_IDL_17_12_TerA15.1@3080.36,8473.94 ; R2R_IDL_17_12_TerA1.1@3034.15,6464.03 3038.63,6459.55 CR_IDL_17_12_TerA1.1@3072.79,6459.55 ; R2R_IDL_17_12_TerA19.1@3035.21,8980.21 3038.99,8976.43 3047.79,8967.64 CR_IDL_17_12_TerA19.1@3086.06,8967.64 ; R2R_IDL_17_12_TerA22.1@3035.21,9282.72 3035.3,9282.64 3037.98,9282.64 CR_IDL_17_12_TerA22.1@3086.06,9282.64 ; R2R_IDL_17_12_TerA20.1@3036.37,9075.44 3039.17,9072.64 CR_IDL_17_12_TerA20.1@3086.06,9072.64 ; R2R_IDL_17_12_TerA16.1@3036.95,8659.7 3042.02,8654.64 CR_IDL_17_12_TerA16.1@3086.06,8654.64 ; R2R_IDL_17_12_TerA18.1@3038.12,8866.99 3042.46,8862.64 CR_IDL_17_12_TerA18.1@3086.06,8862.64 3125.41,8862.64 3127.74,8862.64 v1@3128.92,8861.46 ; R2R_IDL_17_12_TerA23.1@3038.7,9391.3 3042.36,9387.64 CR_IDL_17_12_TerA23.1@3085.18,9387.64 ; CR_IDL_17_12_TerA2.1@3071.34,6571.16 3072.1,6571.92 3074.72,6571.92 v1(3116.75,6571.92) ; CR_IDL_17_12_TerA13.1@3073.58,8146.05 3075.44,8147.91 3092.93,8165.4 v1(3124.13,8165.4) ; CR_IDL_17_12_TerA3.1@3075.6,6675.04 3092.3,6691.74 v1(3117.74,6691.74) ; CR_IDL_17_12_TerA11.1@3076.95,7862.23 3076.95,7865.32 v1(3110.95,7899.32) ; CR_IDL_17_12_TerA1.1@3078.3,6457.29 3080.14,6459.13 3088.48,6467.47 v1(3125.83,6467.47) ; CR_IDL_17_12_TerA1.1@3078.3,6459.55 CR_IDL_17_12_TerA1.1@3072.79,6459.55 ; CR_IDL_17_12_TerA4.1@3078.3,6776.17 3078.82,6776.68 3091.76,6789.62 3092.56,6788.82 v1(3121.14,6788.82) ; CR_IDL_17_12_TerA8.1@3078.3,7207.63 3088.05,7217.38 v1(3088.05,7237.82) ; CR_IDL_17_12_TerA14.1@3078.3,8245.15 3080.75,8247.6 3105.64,8272.5 v1(3105.64,8303.35) ; CR_IDL_17_12_TerA12.1@3078.97,8043.58 CR_IDL_17_12_TerA12.1@3080.32,8042.23 ; CR_IDL_17_12_TerA1.1@3079.1,6453.24 3076.25,6456.08 CR_IDL_17_12_TerA1.1@3072.79,6459.55 ; CR_IDL_17_12_TerA5.1@3079.65,6885.38 3079.65,6885.78 3079.65,6888.32 v1(3109.65,6918.32) ; CR_IDL_17_12_TerA10.1@3079.65,7671.45 3097.38,7689.18 v1(3097.38,7716.14) ; CR_IDL_17_12_TerA12.1@3079.65,8041.56 3086.92,8034.29 v1(3125.84,8034.29) ; CR_IDL_17_12_TerA9.1@3080.32,7460.44 3096.53,7476.65 v1(3096.53,7516.84) ; CR_IDL_17_12_TerA6.1@3080.99,6988.53 3103.8,7011.33 v1(3117.26,7011.33) ; CR_IDL_17_12_TerA7.1@3083.69,7093.02 3097.2,7093.02 v1(3122.56,7118.38) ; CR_IDL_17_12_TerA15.1@3084.98,8471.9 3108.49,8495.41 v1(3108.49,8525.22) ; v1(3085.18,9426.64) CR_IDL_17_12_TerA23.1@3085.18,9387.64 ; CR_IDL_17_12_TerA22.1@3085.31,9278.75 3087.63,9281.07 3116.4,9309.85 v1(3121.7,9309.85) ; CR_IDL_17_12_TerA23.1@3086.09,9385.78 3085.18,9386.69 CR_IDL_17_12_TerA23.1@3085.18,9387.64 ; CR_IDL_17_12_TerA19.1@3086.13,8968.39 3086.47,8968.05 3087.07,8967.45 v1(3130,8967.45) ; CR_IDL_17_12_TerA17.1@3087.19,8751.81 3089.54,8754.16 3103.1,8767.72 3103.61,8767.2 v1(3124.81,8767.2) ; CR_IDL_17_12_TerA20.1@3088.77,9071.37 3109.36,9091.96 v1(3126.89,9091.96) ; CR_IDL_17_12_TerA16.1@3089.72,8653.04 3096.07,8659.39 v1(3128.31,8659.39) ; CR_IDL_17_12_TerA21.1@3090.78,9178.17 3113.52,9200.9 v1(3122.74,9200.9)
  other v1: 113.38,3755.48 49.31,6435.27 3125.41,8863.8 1729.97,9128.74 47.78,9425.41
IACKIN_5: Jtop1.A21 Jtop2.A21 Jtop3.A21 Jtop4.A21 | length 2517.6
  Mid Signal w8: Jtop4.A21@288.16,7354.97 328.08,7354.97 370.57,7397.45 1043.03,7397.45 Jtop3.A21@1085.82,7354.66 ; Jtop3.A21@1088.16,7354.97 1085.73,7352.53 1083.69,7352.53 Jtop3.A21@1085.82,7354.66 ; Jtop1.A21@2688.16,7354.97 2682.75,7354.97 2682.75,7357.79 2647.31,7393.23 2642.77,7393.23 2636.63,7399.37 2061.23,7399.37 2060.34,7398.48 1956.97,7398.48 1913.45,7354.97 Jtop2.A21@1888.16,7354.97 1847.88,7354.97 1805.4,7397.45 1128.6,7397.45 1087.14,7355.99 Jtop3.A21@1085.82,7354.66
IACKOUT_5: Jtop1.A22 Jtop2.A22 Jtop3.A22 Jtop4.A22 | length 2513.4
  Mid Signal w8: Jtop4.A22@288.16,7254.97 328.08,7254.97 370.57,7297.45 979.18,7297.45 1020.99,7255.63 1088.16,7255.63 1089.94,7255.63 Jtop3.A22@1089.99,7255.46 ; Jtop3.A22@1089.99,7255.45 1090.6,7253.15 1133.11,7295.66 1168.78,7295.66 1170.57,7297.45 1205.76,7297.45 1207.54,7295.66 1268.78,7295.66 1270.57,7297.45 1305.76,7297.45 1348.24,7254.97 1691.41,7254.97 1695.1,7258.65 1884.47,7258.65 Jtop2.A22@1888.16,7254.97 1916.53,7254.97 1960.05,7298.48 2644.76,7298.48 2685.44,7257.81 Jtop1.A22@2688.16,7254.97
JB1: Jbot1.B30 Jbot2.B30 Jbot3.B30 Jbot4.B30 R1RB_IDL_17_12_TerB1.1 R2RB_IDL_17_12_TerB1.2 | length 2787.4
  Bot Signal w8: R2RB_IDL_17_12_TerB1.2@206.75,1257.82 206.75,1204.96 206.75,1204.89 206.97,1204.67 R1RB_IDL_17_12_TerB1.1@209.93,1201.7 ; R1RB_IDL_17_12_TerB1.1@207.26,1204.96 228.09,1204.96 270.57,1162.49 305.76,1162.49 348.24,1204.96 384.45,1204.96 386.3,1203.11 Jbot4.B30@386.45,1202.96 ; Jbot4.B30@388.16,1204.96 400.33,1204.96 452.97,1257.6 1138.16,1257.6 Jbot3.B30@1179.54,1216.23 ; Jbot3.B30@1188.16,1204.97 1194.11,1204.97 1244.09,1154.99 1947.49,1154.99 Jbot2.B30@1992.18,1199.68 ; Jbot2.B30@1988.16,1204.97 2009.43,1204.97 2058.24,1253.78 2740.64,1253.78 2788.12,1206.3 Jbot1.B30@2788.16,1204.96
JB2: Jbot1.B29 Jbot2.B29 Jbot3.B29 Jbot4.B29 R1RB_IDL_17_12_TerB2.1 R2RB_IDL_17_12_TerB2.2 | length 2804.3
  Bot Signal w8: R2RB_IDL_17_12_TerB2.2@206.06,1365.3 204.47,1360.99 R2RB_IDL_17_12_TerB2.2@206.57,1363.09 ; R1RB_IDL_17_12_TerB2.1@206.57,1312.44 R2RB_IDL_17_12_TerB2.2@206.57,1363.09 ; Jbot4.B29@389.47,1306.27 Jbot4.B29@390.78,1304.97 ; Jbot4.B29@391.07,1304.67 Jbot4.B29@390.78,1304.97 ; Jbot2.B29@1969.28,1304.96 1969.28,1309.73 Jbot2.B29@1987.42,1309.73 ; Jbot2.B29@1987.8,1307.45 1986.74,1306.39 1937.39,1257.05 1229.72,1257.05 1184.98,1301.79 1182.49,1304.28 1183.6,1306.9 1183.93,1307.66 1144.14,1347.45 459.02,1347.45 416.54,1304.97 Jbot4.B29@390.78,1304.97 ; Jbot2.B29@1988.6,1303.68 1989.02,1304.1 2032.36,1347.45 2705.76,1347.45 2748.24,1304.96 Jbot1.B29@2788.16,1304.96 ; R2RB_IDL_17_12_TerB2.2@206.57,1363.09 207.41,1363.93 240.61,1363.93 257.1,1347.45 305.76,1347.45 348.24,1304.97 Jbot4.B29@388.16,1304.97 Jbot4.B29@390.78,1304.97
JB3: Jbot1.B28 Jbot2.B28 Jbot3.B28 Jbot4.B28 R1RB_IDL_17_12_TerB3.1 R2RB_IDL_17_12_TerB3.2 | length 2786.1
  Bot Signal w8: R1RB_IDL_17_12_TerB3.1@206.57,1417.44 207.76,1419.47 206.06,1421.18 R2RB_IDL_17_12_TerB3.2@206.06,1470.3 262.75,1470.3 270.56,1462.49 326.32,1462.49 386,1402.81 386.82,1401.99 Jbot4.B28@388.16,1404.97 408.34,1404.97 459.59,1456.21 1136.51,1456.21 Jbot3.B28@1186.16,1406.56 ; Jbot3.B28@1188.16,1404.97 1236.22,1356.91 1934.25,1356.91 1985.23,1407.89 Jbot2.B28@1985.56,1408.22 ; Jbot2.B28@1989.05,1398.94 1991.62,1401.51 2043.32,1453.21 2739.92,1453.21 Jbot1.B28@2788.16,1404.97
JB4: Jbot1.B27 Jbot2.B27 Jbot3.B27 Jbot4.B27 R1RB_IDL_17_12_TerB4.1 R2RB_IDL_17_12_TerB4.2 | length 2769.7
  Bot Signal w8: R1RB_IDL_17_12_TerB4.1@208.82,1514.29 206.12,1516.99 206.06,1517.06 206.06,1517.44 R2RB_IDL_17_12_TerB4.2@206.06,1570.3 262.76,1570.3 270.57,1562.49 329.62,1562.49 387.65,1504.46 Jbot4.B27@388.41,1503.7 ; Jbot4.B27@388.16,1504.97 404.08,1504.97 451.31,1552.21 1136.51,1552.21 Jbot3.B27@1181.2,1507.52 ; Jbot3.B27@1188.16,1504.97 1235.26,1457.87 1939.21,1457.87 Jbot2.B27@1987.21,1505.86 ; Jbot2.B27@1988.16,1504.97 1991.97,1504.97 2035.18,1548.17 2751.49,1548.17 Jbot1.B27@2788.12,1511.54
JB5: Jbot1.B26 Jbot2.B26 Jbot3.B26 Jbot4.B26 R1RB_IDL_17_12_TerB5.1 R2RB_IDL_17_12_TerB5.2 | length 2766.5
  Bot Signal w8: R2RB_IDL_17_12_TerB5.2@205.81,1671.63 206.57,1670.87 R2RB_IDL_17_12_TerB5.2@206.57,1670.3 ; R1RB_IDL_17_12_TerB5.1@206.57,1617.44 R2RB_IDL_17_12_TerB5.2@206.57,1670.3 ; Jbot4.B26@388.16,1604.96 386.29,1604.35 348.85,1604.35 305.76,1647.45 251.02,1647.45 228.17,1670.3 R2RB_IDL_17_12_TerB5.2@206.57,1670.3 ; Jbot4.B26@388.42,1610.13 425.74,1647.45 1145.68,1647.45 Jbot3.B26@1188.16,1604.97 ; Jbot3.B26@1189.47,1606.82 1189.74,1606.55 1235.81,1560.48 1942.52,1560.48 1987.01,1604.96 Jbot2.B26@1988.16,1604.96 ; Jbot2.B26@1993.12,1606.51 2039.25,1652.64 2740.49,1652.64 Jbot1.B26@2788.16,1604.97
JB6: Jbot1.B25 Jbot2.B25 Jbot3.B25 Jbot4.B25 R1RB_IDL_17_12_TerB6.1 R2RB_IDL_17_12_TerB6.2 | length 2820.8
  Bot Signal w8: R1RB_IDL_17_12_TerB6.1@206.18,1712.42 206.06,1712.54 206.06,1717.44 R2RB_IDL_17_12_TerB6.2@206.06,1770.3 262.75,1770.3 270.57,1762.48 328.28,1762.48 Jbot4.B25@386.82,1703.94 ; Jbot4.B25@388.16,1704.96 428.08,1704.96 470.57,1747.45 1105.76,1747.45 1105.8,1747.4 1145.07,1747.4 Jbot3.B25@1184.28,1708.2 ; Jbot3.B25@1182.49,1705.76 Jbot3.B25@1184.28,1703.97 ; Jbot3.B25@1190.99,1701.49 1187.84,1704.64 Jbot3.B25@1184.28,1708.2 ; Jbot1.B25@2788.16,1704.96 2745.68,1747.45 2023.2,1747.45 1987.42,1711.66 1979.28,1711.66 1979.28,1704.97 Jbot2.B25@1988.16,1704.97 1988.16,1690.76 1957.89,1660.49 1227.75,1660.49 Jbot3.B25@1185.72,1702.53 ; Jbot3.B25@1184.28,1703.97 1184.28,1704.97 Jbot3.B25@1184.28,1708.2 ; Jbot3.B25@1184.28,1703.97 1184.28,1702.53 Jbot3.B25@1185.72,1702.53 ; Jbot3.B25@1184.28,1703.97 Jbot3.B25@1185.72,1702.53
JB7: Jbot1.B24 Jbot2.B24 Jbot3.B24 Jbot4.B24 R1RB_IDL_17_12_TerB7.1 R2RB_IDL_17_12_TerB7.2 | length 2775.9
  Bot Signal w8: R1RB_IDL_17_12_TerB7.1@209.35,1826.84 206.06,1830.14 R2RB_IDL_17_12_TerB7.2@206.06,1873.3 259.75,1873.3 270.57,1862.48 329.99,1862.48 Jbot4.B24@384.7,1807.77 ; Jbot4.B24@388.16,1804.97 416.09,1804.97 461.24,1850.12 1148.1,1850.12 Jbot3.B24@1186.16,1812.05 ; Jbot3.B24@1188.16,1804.97 1188.16,1801.77 1237.47,1752.47 1932.59,1752.47 1986.63,1806.5 Jbot2.B24@1992.18,1812.05 ; Jbot2.B24@1988.16,1804.96 2007.07,1804.96 2058.24,1856.14 2739.28,1856.14 Jbot1.B24@2785.41,1810.01
JB8: Jbot1.B23 Jbot2.B23 Jbot3.B23 Jbot4.B23 R1RB_IDL_17_12_TerB8.1 R2RB_IDL_17_12_TerB8.2 | length 2796.8
  Bot Signal w8: R1RB_IDL_17_12_TerB8.1@206.57,1920.44 206.57,1966.93 208.69,1969.06 R2RB_IDL_17_12_TerB8.2@206.06,1973.3 259.76,1973.3 270.57,1962.49 325.03,1962.49 385.36,1902.16 Jbot4.B23@387.77,1899.75 ; Jbot4.B23@388.16,1904.96 400.19,1904.96 456.32,1961.1 1127.41,1961.1 1185.69,1902.82 Jbot3.B23@1188.16,1904.97 1190.36,1904.53 1245.47,1849.42 1914.6,1849.42 1970.14,1904.97 1981.51,1904.97 1981.51,1906.5 1988.16,1906.5 2029.62,1906.5 2070.57,1947.45 2745.68,1947.45 Jbot1.B23@2788.16,1904.97
JB9: Jbot1.B21 Jbot2.B21 Jbot3.B21 Jbot4.B21 R1RB_IDL_17_12_TerB9.1 R2RB_IDL_17_12_TerB9.2 | length 2790.4
  Bot Signal w8: R2RB_IDL_17_12_TerB9.2@206.06,2073.3 208.27,2072.07 207.77,2071.58 206.57,2070.38 R1RB_IDL_17_12_TerB9.1@206.57,2020.44 234.53,2020.44 270.23,2056.14 341.04,2056.14 389.01,2104.11 392.39,2107.48 Jbot4.B21@388.16,2104.96 ; Jbot4.B21@383.46,2113.27 421.52,2151.34 1141.79,2151.34 Jbot3.B21@1188.16,2104.97 ; Jbot3.B21@1199.4,2106.65 1247.4,2058.65 1937.56,2058.65 1983.87,2104.97 Jbot2.B21@1988.16,2104.97 2004.53,2104.97 2048.74,2149.18 2740.64,2149.18 2786.51,2103.31 2788.12,2101.69 Jbot1.B21@2788.16,2104.96
JB10: Jbot1.B20 Jbot2.B20 Jbot3.B20 Jbot4.B20 R1RB_IDL_17_12_TerB10.1 R2RB_IDL_17_12_TerB10.2 | length 2796.6
  Bot Signal w8: R2RB_IDL_17_12_TerB10.2@206.06,2173.3 204.13,2172.4 204.64,2171.89 206.57,2169.96 R1RB_IDL_17_12_TerB10.1@206.57,2120.44 240.69,2120.44 276.72,2156.46 339.27,2156.46 Jbot4.B20@387.97,2205.16 ; Jbot4.B20@390.13,2205.6 436.82,2252.3 1144.78,2252.3 1187.82,2209.26 Jbot3.B20@1188.16,2204.97 1188.16,2198.99 1230.85,2156.3 1939.21,2156.3 1988.02,2205.11 1988.87,2205.95 1990.41,2208.87 2036.53,2255 2724.36,2255 2774.39,2204.96 Jbot1.B20@2788.16,2204.96
JB11: Jbot1.B19 Jbot2.B19 Jbot3.B19 Jbot4.B19 R1RB_IDL_17_12_TerB11.1 R2RB_IDL_17_12_TerB11.2 | length 2789.6
  Bot Signal w8: R2RB_IDL_17_12_TerB11.2@206.06,2278.3 206.06,2228.64 R1RB_IDL_17_12_TerB11.1@207.61,2227.08 ; R1RB_IDL_17_12_TerB11.1@206.57,2225.44 237.11,2225.44 269.05,2257.37 343.99,2257.37 389.87,2303.25 Jbot4.B19@390.02,2303.4 ; Jbot4.B19@388.16,2304.97 414.61,2304.97 462.9,2353.25 1136.51,2353.25 Jbot3.B19@1184.51,2305.26 ; Jbot3.B19@1188.16,2304.97 1237.52,2255.61 1939.21,2255.61 1988.37,2304.76 Jbot2.B19@1988.57,2304.96 ; Jbot2.B19@1988.16,2304.96 Jbot2.B19@1988.57,2304.96 ; Jbot1.B19@2788.16,2304.97 2789.48,2306.55 2740.64,2355.39 2060.95,2355.39 2010.53,2304.96 Jbot2.B19@1988.57,2304.96
JB12: Jbot1.B18 Jbot2.B18 Jbot3.B18 Jbot4.B18 R1RB_IDL_17_12_TerB12.1 R2RB_IDL_17_12_TerB12.2 | length 2785.8
  Bot Signal w8: R1RB_IDL_17_12_TerB12.1@205.9,2324.28 206.06,2324.43 206.06,2325.44 R2RB_IDL_17_12_TerB12.2@206.06,2378.3 ; R1RB_IDL_17_12_TerB12.1@206.57,2325.44 238.56,2325.44 267.87,2354.75 341.63,2354.75 390.01,2403.12 Jbot4.B18@391.2,2404.32 ; Jbot4.B18@388.16,2404.97 395.42,2404.97 447.02,2456.57 1137.69,2456.57 1182.87,2411.38 1184.2,2412.71 1190.05,2406.86 1230.68,2366.23 1266.82,2366.23 1270.57,2362.48 1905.76,2362.48 1948.24,2404.97 Jbot2.B18@1988.16,2404.97 2028.08,2404.97 2070.57,2447.45 2751.31,2447.45 Jbot1.B18@2789.96,2408.8
JB13: Jbot1.B17 Jbot2.B17 Jbot3.B17 Jbot4.B17 R1RB_IDL_17_12_TerB13.1 R2RB_IDL_17_12_TerB13.2 | length 2787
  Bot Signal w8: R2RB_IDL_17_12_TerB13.2@206.06,2478.3 206.06,2427.63 207.41,2426.28 238.23,2457.1 252.89,2457.1 ; 251.34,2457.43 343.99,2457.43 388.84,2502.28 Jbot4.B17@388.16,2504.96 389.49,2504.59 391.39,2504.06 434.78,2547.45 1117.37,2547.45 1159.85,2504.97 Jbot3.B17@1188.16,2504.97 Jbot3.B17@1190.03,2504.97 ; Jbot3.B17@1189.06,2505.94 1189.09,2505.9 Jbot3.B17@1190.03,2504.97 ; Jbot1.B17@2788.16,2504.96 2748.24,2504.96 2705.76,2547.45 2025.76,2547.45 1989.82,2511.51 1989.28,2511.51 1989.28,2506.08 Jbot2.B17@1988.16,2504.96 1988.08,2500.5 1945.05,2457.47 1237.53,2457.47 Jbot3.B17@1190.03,2504.97
JB14: Jbot1.B16 Jbot2.B16 Jbot3.B16 Jbot4.B16 R1RB_IDL_17_12_TerB14.1 R2RB_IDL_17_12_TerB14.2 | length 2778.2
  Bot Signal w8: R2RB_IDL_17_12_TerB14.2@204.72,2577.81 R2RB_IDL_17_12_TerB14.2@206.06,2577.81 ; R1RB_IDL_17_12_TerB14.1@206.57,2525.44 206.19,2526.64 206.06,2526.77 R2RB_IDL_17_12_TerB14.2@206.06,2577.81 ; Jbot3.B16@1187.82,2604.82 1144.78,2647.86 449.66,2647.86 406.77,2604.96 Jbot4.B16@388.16,2604.96 348.24,2604.96 305.76,2562.48 270.57,2562.48 255.24,2577.81 R2RB_IDL_17_12_TerB14.2@206.06,2577.81 ; Jbot3.B16@1188.16,2604.97 1192.64,2604.97 1245.74,2551.86 1937.56,2551.86 Jbot2.B16@1985.56,2599.86 ; Jbot2.B16@1988.16,2604.97 1991.76,2605.01 2044.67,2657.92 2735.2,2657.92 Jbot1.B16@2788.16,2604.96
JB15: Jbot1.B15 Jbot2.B15 Jbot3.B15 Jbot4.B15 R1RB_IDL_17_12_TerB15.1 R2RB_IDL_17_12_TerB15.2 | length 2778.6
  Bot Signal w8: R1RB_IDL_17_12_TerB15.1@205.9,2628.96 206.06,2629.11 R2RB_IDL_17_12_TerB15.2@206.06,2678.3 ; R1RB_IDL_17_12_TerB15.1@206.57,2625.44 244.68,2625.44 276.13,2656.89 344.58,2656.89 Jbot4.B15@390.02,2702.33 ; Jbot4.B15@388.16,2704.97 436.42,2753.22 1099.98,2753.22 1145.76,2707.44 Jbot3.B15@1184.51,2707.44 ; Jbot3.B15@1188.16,2704.97 1230.64,2662.49 1952.19,2662.49 1991.41,2701.71 Jbot2.B15@1997.14,2707.44 ; Jbot2.B15@1988.16,2704.96 1994.03,2704.96 2040.6,2751.53 2744.71,2751.53 Jbot1.B15@2785.41,2710.83
JB16: Jbot1.B14 Jbot2.B14 Jbot3.B14 Jbot4.B14 R1RB_IDL_17_12_TerB16.1 R2RB_IDL_17_12_TerB16.2 | length 2819.8
  Bot Signal w8: R2RB_IDL_17_12_TerB16.2@206.06,2783.3 206.06,2733.12 207.65,2731.53 R1RB_IDL_17_12_TerB16.1@208.74,2730.44 ; R1RB_IDL_17_12_TerB16.1@206.57,2730.44 R1RB_IDL_17_12_TerB16.1@208.74,2730.44 ; R1RB_IDL_17_12_TerB16.1@209.04,2730.14 R1RB_IDL_17_12_TerB16.1@208.74,2730.44 ; Jbot4.B14@387.74,2804.61 Jbot4.B14@388.13,2805 ; Jbot1.B14@2788.16,2804.97 2791.61,2806.38 2788.16,2806.38 2746.82,2806.38 2705.76,2847.45 2070.57,2847.45 2028.08,2804.97 Jbot2.B14@1988.16,2804.97 1988.16,2798.38 1943.32,2753.54 1227.23,2753.54 1184.2,2796.58 1188.16,2796.58 Jbot3.B14@1188.16,2804.97 1194.68,2804.97 1194.68,2805.29 1191.58,2808.39 1152.53,2847.45 430.58,2847.45 388.15,2805.01 387.66,2807.37 386.71,2806.42 386.32,2806.03 338.09,2757.8 273.18,2757.8 245.81,2730.44 R1RB_IDL_17_12_TerB16.1@208.74,2730.44
JB17: Jbot1.B11 Jbot2.B11 Jbot3.B11 Jbot4.B11 R1RB_IDL_17_12_TerB17.1 R2RB_IDL_17_12_TerB17.2 | length 2899.2
  Bot Signal w8: R2RB_IDL_17_12_TerB17.2@206.06,2883.3 206.06,2888.14 280.4,2962.49 305.76,2962.49 330.64,2987.37 330.64,3047.81 Jbot4.B11@387.91,3105.08 ; R2RB_IDL_17_12_TerB17.2@206.19,2886.9 206.57,2886.52 206.57,2883.3 R1RB_IDL_17_12_TerB17.1@206.57,2830.44 ; Jbot4.B11@389.33,3106.5 387.98,3105.15 Jbot4.B11@387.91,3105.08 ; Jbot3.B11@1188.07,3105.2 1160.85,3132.42 1120.78,3132.42 1105.76,3147.45 470.57,3147.45 428.08,3104.97 Jbot4.B11@388.16,3104.97 Jbot4.B11@387.91,3105.08 ; Jbot3.B11@1188.16,3104.97 Jbot3.B11@1192.24,3104.97 ; Jbot3.B11@1190.04,3107.17 1190.2,3107.01 Jbot3.B11@1192.24,3104.97 ; Jbot1.B11@2788.16,3104.96 2748.24,3104.96 2705.76,3147.45 2070.57,3147.45 2029.34,3106.22 1989.82,3106.22 Jbot2.B11@1988.16,3104.96 1990.28,3102.85 1990.28,3096.1 1991.52,3096.1 1946.77,3051.34 1258.22,3051.34 1204.59,3104.97 Jbot3.B11@1192.24,3104.97
JB18: Jbot1.B10 Jbot2.B10 Jbot3.B10 Jbot4.B10 R1RB_IDL_17_12_TerB18.1 R2RB_IDL_17_12_TerB18.2 | length 2936.3
  Bot Signal w8: R1RB_IDL_17_12_TerB18.1@205.91,2931.09 206.06,2931.23 R2RB_IDL_17_12_TerB18.2@206.06,2983.3 206.06,2986.83 281.71,3062.49 305.76,3062.49 330.64,3087.37 330.64,3145.68 Jbot4.B10@388.06,3203.09 ; Jbot4.B10@388.06,3207.7 388.06,3204.97 Jbot4.B10@388.06,3203.09 ; Jbot4.B10@388.16,3204.97 Jbot4.B10@389.04,3204.08 ; Jbot4.B10@389.65,3204.68 Jbot4.B10@389.05,3204.08 ; Jbot4.B10@391.58,3201.51 Jbot4.B10@389.04,3204.08 ; Jbot4.B10@391.6,3201.53 442.06,3251.99 1122.27,3251.99 1169.3,3204.97 Jbot3.B10@1188.16,3204.97 1228.09,3204.97 1270.57,3162.49 1363.6,3162.49 1415.43,3110.66 1833.78,3110.66 1870.57,3147.45 1924.99,3147.45 1979.97,3202.43 1978.17,3204.96 Jbot2.B10@1988.16,3204.96 2028.08,3204.96 2070.57,3247.45 2746.47,3247.45 2788.56,3205.36 2789.96,3203.96 2789.96,3204.97 2789.96,3207.28 Jbot1.B10@2793.27,3207.28 ; Jbot4.B10@388.06,3203.09 Jbot4.B10@389.04,3204.08
JB19: Jbot1.B9 Jbot2.B9 Jbot3.B9 Jbot4.B9 R1RB_IDL_17_12_TerB19.1 R2RB_IDL_17_12_TerB19.2 | length 2920.7
  Bot Signal w8: R1RB_IDL_17_12_TerB19.1@205.8,3029.41 206.06,3029.67 206.06,3030.44 R2RB_IDL_17_12_TerB19.2@206.06,3083.3 206.06,3091.67 276.87,3162.48 305.76,3162.48 330.64,3187.37 330.64,3216.25 387.55,3273.16 387.55,3304.96 Jbot4.B9@387.55,3311 ; Jbot4.B9@388.16,3304.96 396.57,3304.96 444.9,3353.3 1142.35,3353.3 Jbot3.B9@1185.47,3310.18 ; Jbot3.B9@1188.16,3304.97 1239.52,3253.61 1350.01,3253.61 1353.32,3250.3 1364.91,3250.3 1399.66,3285.05 1773.71,3285.05 1803.5,3255.26 1944.18,3255.26 1991.02,3302.11 1992.18,3303.26 Jbot2.B9@1988.16,3304.97 ; Jbot2.B9@1991.76,3309.12 2035.18,3352.54 2732.5,3352.54 2780.07,3304.97 Jbot1.B9@2788.16,3304.97
JB20: Jbot1.B8 Jbot2.B8 Jbot3.B8 Jbot4.B8 R1RB_IDL_17_12_TerB20.1 R2RB_IDL_17_12_TerB20.2 | length 2918.2
  Bot Signal w8: R1RB_IDL_17_12_TerB20.1@206.57,3135.44 204.58,3136.02 205.28,3136.72 206.06,3137.5 R2RB_IDL_17_12_TerB20.2@206.06,3188.3 280.24,3262.48 305.76,3262.48 330.64,3287.37 330.64,3344.95 Jbot4.B8@387.4,3401.71 ; Jbot4.B8@388.16,3404.96 389.67,3406.47 389.67,3409.94 434.95,3455.22 1137.91,3455.22 Jbot3.B8@1188.16,3404.97 1188.16,3422.73 1201.41,3422.73 1201.41,3411.11 1250.04,3362.48 1905.76,3362.48 1948.24,3404.96 Jbot2.B8@1988.16,3404.96 2028.08,3404.96 2070.57,3447.45 2756.86,3447.45 2793.27,3411.04 2788.16,3411.04 Jbot1.B8@2788.16,3404.96
JB21: Jbot1.B7 Jbot2.B7 Jbot3.B7 Jbot4.B7 R1RB_IDL_17_12_TerB21.1 R2RB_IDL_17_12_TerB21.2 | length 2989.1
  Bot Signal w8: R1RB_IDL_17_12_TerB21.1@206.57,3235.44 206.57,3283.6 208.6,3285.64 R2RB_IDL_17_12_TerB21.2@206.06,3288.3 230.01,3288.3 244.29,3302.57 245.68,3303.61 245.68,3322.56 285.61,3362.49 305.76,3362.49 330.64,3387.37 330.64,3420.34 388.16,3477.85 Jbot4.B7@388.16,3504.96 428.08,3504.96 470.57,3547.45 1105.76,3547.45 1106.32,3546.88 1139.52,3546.88 1181.49,3504.92 1181.49,3504.97 Jbot3.B7@1188.16,3504.97 ; Jbot3.B7@1195.99,3506.64 1255.19,3447.45 1305.76,3447.45 1357.27,3395.93 1745.57,3395.93 1797.09,3447.44 1905.76,3447.44 1906.41,3446.8 1929.99,3446.8 Jbot2.B7@1988.16,3504.97 ; 1948.23,3462.48 1988.08,3502.34 Jbot2.B7@1988.16,3504.97 ; Jbot1.B7@2788.16,3504.96 2748.24,3504.96 2705.76,3547.45 2670.57,3547.45 2668.34,3545.22 2107.98,3545.22 2105.76,3547.45 2028.49,3547.45 1988.16,3507.12 Jbot2.B7@1988.16,3504.97
JB22: Jbot1.B6 Jbot2.B6 Jbot3.B6 Jbot4.B6 R1RB_IDL_17_12_TerB22.1 R2RB_IDL_17_12_TerB22.2 | length 2909.6
  Bot Signal w8: R1RB_IDL_17_12_TerB22.1@206.57,3333.44 206.57,3386.3 R2RB_IDL_17_12_TerB22.2@206.57,3386.81 ; R2RB_IDL_17_12_TerB22.2@208.44,3388.93 206.57,3387.05 R2RB_IDL_17_12_TerB22.2@206.57,3386.81 ; Jbot4.B6@388.16,3604.97 388.3,3605.2 389.74,3607.58 389.74,3604.97 Jbot4.B6@389.74,3603.96 ; Jbot4.B6@389.97,3604.2 Jbot4.B6@389.74,3603.96 ; Jbot4.B6@392.13,3605.19 434.39,3647.45 1188.16,3647.45 Jbot3.B6@1188.16,3604.97 ; Jbot3.B6@1190.16,3606.4 1238.91,3557.66 1940.86,3557.66 Jbot2.B6@1988.16,3604.96 1999.99,3604.96 2052.81,3657.78 2733.86,3657.78 2787.42,3604.22 2788.12,3603.52 Jbot1.B6@2788.16,3604.96 ; R2RB_IDL_17_12_TerB22.2@206.57,3386.81 282.24,3462.48 305.76,3462.48 330.64,3487.37 330.64,3544.87 389.45,3603.68 Jbot4.B6@389.74,3603.96
JB23: Jbot1.B5 Jbot2.B5 Jbot3.B5 Jbot4.B5 R1RB_IDL_17_12_TerB23.1 R2RB_IDL_17_12_TerB23.2 | length 2882.5
  Bot Signal w8: R1RB_IDL_17_12_TerB23.1@208.3,3426.74 206.06,3428.99 206.06,3433.44 R2RB_IDL_17_12_TerB23.2@206.06,3486.3 209.55,3486.3 246.09,3522.84 ; 245.68,3522.56 278.43,3555.3 300.69,3555.3 330.64,3585.26 330.64,3645.63 389.07,3704.06 Jbot4.B5@389.97,3704.97 ; Jbot4.B5@390.29,3705.29 Jbot4.B5@389.97,3704.97 ; Jbot3.B5@1179.85,3707.65 1130.16,3757.33 449.59,3757.33 397.22,3704.97 Jbot4.B5@389.97,3704.97 ; Jbot3.B5@1188.16,3704.97 1237.04,3656.09 1946.67,3656.09 Jbot2.B5@1991.66,3701.08 ; Jbot2.B5@1988.16,3704.97 2013.17,3704.97 2060.95,3752.75 2747.42,3752.75 Jbot1.B5@2788.12,3712.05
JB24: Jbot1.B4 Jbot2.B4 Jbot3.B4 Jbot4.B4 R1RB_IDL_17_12_TerB24.1 R2RB_IDL_17_12_TerB24.2 | length 2876.3
  Bot Signal w8: R2RB_IDL_17_12_TerB24.2@206.06,3591.3 R2RB_IDL_17_12_TerB24.2@206.57,3591.81 ; R1RB_IDL_17_12_TerB24.1@206.57,3538.44 206.57,3591.3 R2RB_IDL_17_12_TerB24.2@206.57,3591.81 ; 246.15,3634.29 246.15,3631.39 245.68,3630.92 ; Jbot4.B4@391.67,3806.2 435.21,3849.73 1150.1,3849.73 1191.51,3808.32 1237.34,3762.48 1905.76,3762.48 1948.24,3804.97 Jbot2.B4@1988.16,3804.97 2028.08,3804.97 2070.57,3847.45 2705.76,3847.45 2741.27,3811.93 Jbot1.B4@2778.36,3811.93 ; Jbot4.B4@392.25,3805.62 388.16,3805.62 348.89,3805.62 290.71,3747.44 270.57,3747.44 245.68,3722.56 245.68,3630.92 ; R2RB_IDL_17_12_TerB24.2@206.57,3591.81 245.68,3630.92
JB25: Jbot1.B3 Jbot2.B3 Jbot3.B3 Jbot4.B3 R1RB_IDL_17_12_TerB25.1 R2RB_IDL_17_12_TerB25.2 | length 2908.9
  Bot Signal w8: R2RB_IDL_17_12_TerB25.2@205.8,3690.38 206.57,3689.62 R1RB_IDL_17_12_TerB25.1@206.57,3638.44 ; R2RB_IDL_17_12_TerB25.2@206.06,3691.3 206.06,3800.6 258.81,3853.35 335.75,3853.35 387.76,3905.36 Jbot4.B3@389.32,3906.92 ; Jbot4.B3@388.16,3904.96 434.58,3951.38 1145.16,3951.38 Jbot3.B3@1189.87,3906.67 ; Jbot3.B3@1188.16,3904.97 Jbot3.B3@1189.87,3906.67 ; Jbot3.B3@1192.97,3903.57 Jbot3.B3@1189.87,3906.67 ; Jbot2.B3@1982.29,3904.51 1932.6,3954.19 1237.39,3954.19 Jbot3.B3@1189.87,3906.67 ; Jbot2.B3@1988.16,3904.96 1991.76,3906.05 2040.6,3954.89 2738.23,3954.89 Jbot1.B3@2788.16,3904.97
JT1: Jtop1.A30 Jtop2.A30 Jtop3.A30 Jtop4.A30 R1R_IDL_17_12_TerA1.1 R2R_IDL_17_12_TerA1.2 | length 2910.1
  Mid Signal w8: Jtop4.A30@288.16,6454.97 301.14,6454.97 352.35,6506.18 904.99,6506.18 957.62,6453.55 1088,6453.55 Jtop3.A30@1088.16,6454.97 1128.09,6454.97 1170.57,6497.45 1305.76,6497.45 1348.24,6454.97 1609.58,6454.97 1610.14,6455.53 1887.6,6455.53 Jtop2.A30@1888.16,6454.97 1912.92,6454.97 1956.44,6498.48 2631.92,6498.48 2633.55,6496.85 2645.86,6496.85 2687.95,6454.76 Jtop1.A30@2688.05,6454.66 ; Jtop3.A30@1081.1,6463.02 Jtop3.A30@1088.16,6463.02
  Bot Signal w8: Jtop1.A30@2688.16,6454.97 2736.8,6406.33 2987.45,6406.33 R1R_IDL_17_12_TerA1.1@2987.45,6412.3 2987.45,6465.12 2988.99,6466.66 R2R_IDL_17_12_TerA1.2@2993.72,6471.39
JT2: Jtop1.A29 Jtop2.A29 Jtop3.A29 Jtop4.A29 R1R_IDL_17_12_TerA2.1 R2R_IDL_17_12_TerA2.2 | length 2921.5
  Mid Signal w8: Jtop4.A29@288.16,6554.97 303.05,6554.97 357.14,6609.05 1021.02,6609.05 1079.63,6550.44 1079.63,6554.97 Jtop3.A29@1088.16,6554.97 1088.16,6559.81 1085.83,6559.81 1115.46,6589.44 1162.56,6589.44 1170.57,6597.45 1205.76,6597.45 1213.76,6589.44 1244.29,6589.44 1259.42,6604.57 1783.51,6604.57 1833.12,6554.97 Jtop2.A29@1888.16,6554.97 1930.64,6597.45 2644.14,6597.45 2687.39,6554.2 Jtop1.A29@2688.16,6553.43 ; Jtop1.A29@2688.16,6551.12 Jtop1.A29@2688.16,6553.43 ; Jtop1.A29@2688.16,6554.97 2689.27,6552.32 Jtop1.A29@2688.16,6553.43
  Bot Signal w8: Jtop1.A29@2688.16,6554.97 2728.4,6514.73 2753.07,6514.73 2756.07,6511.73 2930.28,6511.73 2942.08,6523.54 R1R_IDL_17_12_TerA2.1@2982.45,6523.54 2982.45,6549.73 2983.33,6550.61 R2R_IDL_17_12_TerA2.2@2983.33,6578.56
